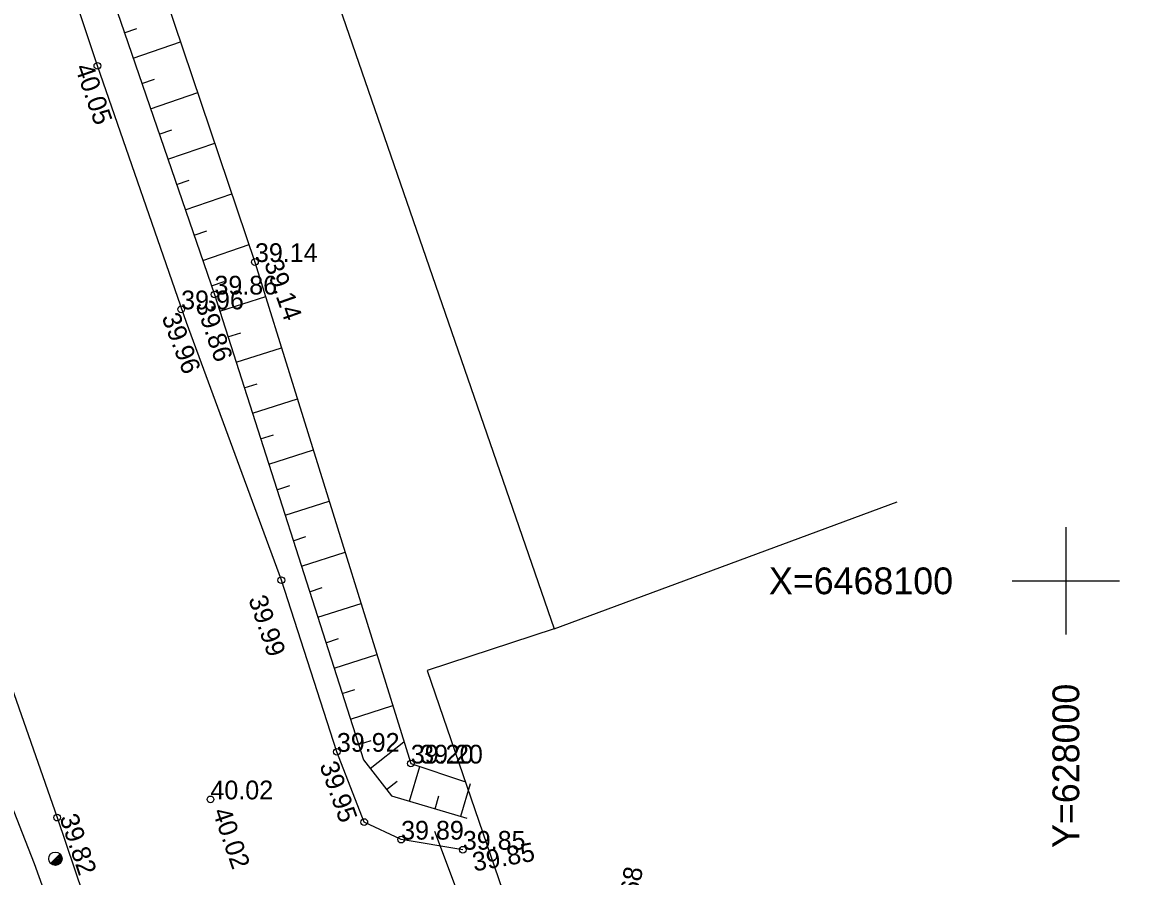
# Model space of a CAD drawing. Extents: x 627548 to 628052, y 6467984 to 6468802.
# Drawn here: x 627961.02 to 628002.94, y 6468088.95 to 6468120.86 of the extents above; entities that cross this region are included whole.
import ezdxf

# ---------------------------------------------------------------- set-up
doc = ezdxf.new("R2010")
doc.units = 0
for name, color, linetype in [('KORGUS-EH2000', 7, 'Continuous'), ('MOOTKORG-EH2000', 7, 'Continuous'), ('MOOTMPUNKT', 7, 'Continuous'), ('PIIR', 7, 'Continuous'), ('POST', 7, 'Continuous'), ('RELJEEF', 7, 'Continuous'), ('TEE', 7, 'Continuous'), ('TRUUP', 7, 'Continuous'), ('VORK', 7, 'Continuous')]:
    doc.layers.add(name, color=color, linetype=linetype)

msp = doc.modelspace()

# ---------------------------------------------------------------- linework, layer by layer
at = {"layer": 'KORGUS-EH2000'}
for centre in [(627963.821, 6468119.239), (627970.692, 6468100.023), (627962.318, 6468091.154), (627973.79, 6468090.987)]:
    msp.add_circle(centre, 0.125, dxfattribs=at)
at = {"layer": 'MOOTMPUNKT'}
for centre in [(627969.706, 6468111.912), (627968.192, 6468110.697), (627966.949, 6468110.144), (627972.767, 6468093.614), (627975.527, 6468093.175), (627968.043, 6468091.836), (627975.167, 6468090.332), (627977.472, 6468089.955)]:
    msp.add_circle(centre, 0.125, dxfattribs=at)
at = {"layer": 'PIIR'}
for p, q in [((627962.62, 6468151.07), (627980.89, 6468098.21)), ((627980.89, 6468098.21), (627993.698, 6468102.952)), ((627980.89, 6468098.21), (627976.14, 6468096.65)), ((627976.14, 6468096.65), (628002.94, 6468018.71))]:
    msp.add_line(p, q, dxfattribs=at)
at = {"layer": 'POST'}
msp.add_line((627962.073, 6468089.443), (627962.427, 6468089.796), dxfattribs=at)
msp.add_circle((627962.25, 6468089.619), 0.25, dxfattribs=at)
for radius, start, end in [(0.225, 224.8541, 45.0356), (0.2, 224.8427, 45.047), (0.175, 224.8281, 45.0616), (0.15, 224.8087, 45.081), (0.125, 224.7814, 45.1083), (0.1, 224.7406, 45.1491), (0.075, 224.6725, 45.2172), (0.05, 224.5363, 45.3534), (0.025, 224.1278, 45.7619)]:
    msp.add_arc((627962.25, 6468089.619), radius, start, end, dxfattribs=at)
at = {"layer": 'RELJEEF'}
for p, q in [((627964.826, 6468120.476), (627965.299, 6468120.639)), ((627965.152, 6468119.53), (627966.927, 6468120.141)), ((627965.477, 6468118.585), (627965.95, 6468118.747)), ((627965.803, 6468117.639), (627967.567, 6468118.246)), ((627966.128, 6468116.694), (627966.601, 6468116.856)), ((627966.454, 6468115.748), (627968.207, 6468116.351)), ((627966.779, 6468114.802), (627967.252, 6468114.965)), ((627967.104, 6468113.857), (627968.847, 6468114.457)), ((627967.43, 6468112.911), (627967.903, 6468113.074)), ((627967.755, 6468111.966), (627969.487, 6468112.562)), ((627968.081, 6468111.02), (627968.554, 6468111.183)), ((627968.393, 6468110.07), (627970.108, 6468110.619)), ((627968.698, 6468109.118), (627969.174, 6468109.27)), ((627969.003, 6468108.165), (627970.701, 6468108.709)), ((627969.308, 6468107.213), (627969.784, 6468107.366)), ((627969.613, 6468106.261), (627971.294, 6468106.799)), ((627969.917, 6468105.308), (627970.394, 6468105.461)), ((627970.222, 6468104.356), (627971.888, 6468104.889)), ((627970.527, 6468103.404), (627971.004, 6468103.556)), ((627970.832, 6468102.451), (627972.481, 6468102.979)), ((627971.137, 6468101.499), (627971.613, 6468101.651)), ((627971.442, 6468100.546), (627973.075, 6468101.069)), ((627971.747, 6468099.594), (627972.223, 6468099.747)), ((627972.052, 6468098.642), (627973.668, 6468099.159)), ((627972.357, 6468097.689), (627972.833, 6468097.842)), ((627972.662, 6468096.737), (627974.261, 6468097.249)), ((627972.967, 6468095.785), (627973.443, 6468095.937)), ((627973.272, 6468094.832), (627974.855, 6468095.339)), ((627973.577, 6468093.88), (627974.053, 6468094.032)), ((627974.007, 6468092.994), (627975.274, 6468093.989)), ((627975.479, 6468091.771), (627975.862, 6468093.064)), ((627974.624, 6468092.207), (627975.018, 6468092.516)), ((627977.397, 6468091.204), (627977.761, 6468092.434)), ((627976.438, 6468091.487), (627976.58, 6468091.967))]:
    msp.add_line(p, q, dxfattribs=at)
for points in [[(627978.291, 6468008.882), (627983.457, 6468013.678), (627984.21, 6468021.024), (627979.575, 6468037.02), (627973.979, 6468054.36), (627968.222, 6468070.605), (627961.466, 6468089.433), (627957.405, 6468099.776), (627954.697, 6468099.952), (627954.601, 6468100.77), (627956.677, 6468103.285), (627952.114, 6468117.091), (627946.482, 6468133.262), (627941.383, 6468147.782), (627936.221, 6468162.714), (627931.414, 6468176.011), (627926.765, 6468189.068), (627921.448, 6468202.325), (627917.805, 6468212.302), (627916.173, 6468214.408), (627912.962, 6468214.481), (627910.459, 6468214.182)], [(627959.925, 6468145.086), (627957.009, 6468143.19), (627968.192, 6468110.697), (627973.76, 6468093.308), (627974.813, 6468091.968), (627977.619, 6468091.138)], [(627961.048, 6468143.048), (627960.319, 6468139.708), (627969.706, 6468111.912), (627975.527, 6468093.175), (627977.537, 6468092.509)]]:
    msp.add_lwpolyline(points, dxfattribs=at)
at = {"layer": 'TEE'}
for points in [[(627977.472, 6468089.955), (627975.167, 6468090.332), (627973.79, 6468090.987), (627972.767, 6468093.614), (627970.692, 6468100.023), (627967.147, 6468109.656), (627963.821, 6468119.239), (627960.6, 6468128.902), (627957.471, 6468138.439), (627955.717, 6468143.383), (627960.478, 6468146.317)], [(627948.73, 6468130.073), (627952.157, 6468120.49), (627955.55, 6468110.522), (627958.987, 6468100.641), (627962.318, 6468091.154), (627965.56, 6468081.571), (627969.012, 6468071.605), (627972.432, 6468061.577), (627975.777, 6468052.007), (627979.213, 6468042.181), (627982.519, 6468032.549), (627985.763, 6468023.005), (627987.717, 6468016.784), (627987.108, 6468013.905), (627990.1, 6468007.105), (627992.636, 6468000.403), (627994.498, 6467998.047), (627996.95, 6467991.167)]]:
    msp.add_lwpolyline(points, dxfattribs=at)
at = {"layer": 'TRUUP'}
msp.add_lwpolyline([(627976.412, 6468090.651), (627978.836, 6468084.189)], dxfattribs=at)
at = {"layer": 'VORK'}
for p, q in [((628000, 6468102), (628000, 6468098)), ((627998, 6468100), (628002, 6468100))]:
    msp.add_line(p, q, dxfattribs=at)

# ---------------------------------------------------------------- texts
at = {"layer": 'KORGUS-EH2000'}
for s, rotation, p in [(' 40.05', 289.1405, (627962.887, 6468119.433)), ('39.14', 289.5164, (627970.042, 6468111.866)), ('39.86', 288.9012, (627967.475, 6468110.338)), ('39.96', 290.9546, (627966.21, 6468109.852)), (' 39.99', 288.9243, (627969.368, 6468099.569)), (' 39.95', 289.6487, (627972.021, 6468093.358)), ('40.02', 289.0524, (627968.115, 6468091.384)), (' 39.82', 288.6911, (627962.313, 6468091.405)), ('39.85', 10.0091, (627977.896, 6468089.141)), (' 39.68', 80.5262, (627983.775, 6468086.689))]:
    msp.add_text(s, height=0.7, rotation=rotation, dxfattribs=at).set_placement(p)
msp.add_text('39.20', height=0.7, dxfattribs=at).set_placement((627975.877, 6468093.175))
at = {"layer": 'MOOTKORG-EH2000'}
for s, p in [('39.14', (627969.706, 6468111.912)), ('39.86', (627968.192, 6468110.697)), ('39.96', (627966.949, 6468110.144)), ('39.92', (627972.767, 6468093.614)), ('39.20', (627975.527, 6468093.175)), ('40.02', (627968.043, 6468091.836)), ('39.89', (627975.167, 6468090.332)), ('39.85', (627977.472, 6468089.955))]:
    msp.add_text(s, height=0.7, dxfattribs=at).set_placement(p)
at = {"layer": 'VORK'}
msp.add_text('X=6468100 ', height=1, dxfattribs=at).set_placement((627988.908, 6468099.5))
msp.add_text('Y=628000 ', height=1, rotation=90, dxfattribs=at).set_placement((628000.5, 6468090.021))

doc.saveas('drawing.dxf')
